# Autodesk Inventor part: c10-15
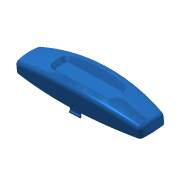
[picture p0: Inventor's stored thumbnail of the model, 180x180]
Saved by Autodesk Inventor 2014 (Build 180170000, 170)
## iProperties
Created: 2011-01
Part Number: c10-15
Material: Generic
Document SubType Name: Modeling
Designer: Thom Tremblay
Density: 1 g/cm^3
Appearance: Cyan
Author: Thom Tremblay
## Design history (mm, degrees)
derived "c10-13.ipt"
feature "Front::c10-13.ipt" dims "d1" = 10
tag "TaggingFeature2"
body "Solid1"
body "Solid2"
